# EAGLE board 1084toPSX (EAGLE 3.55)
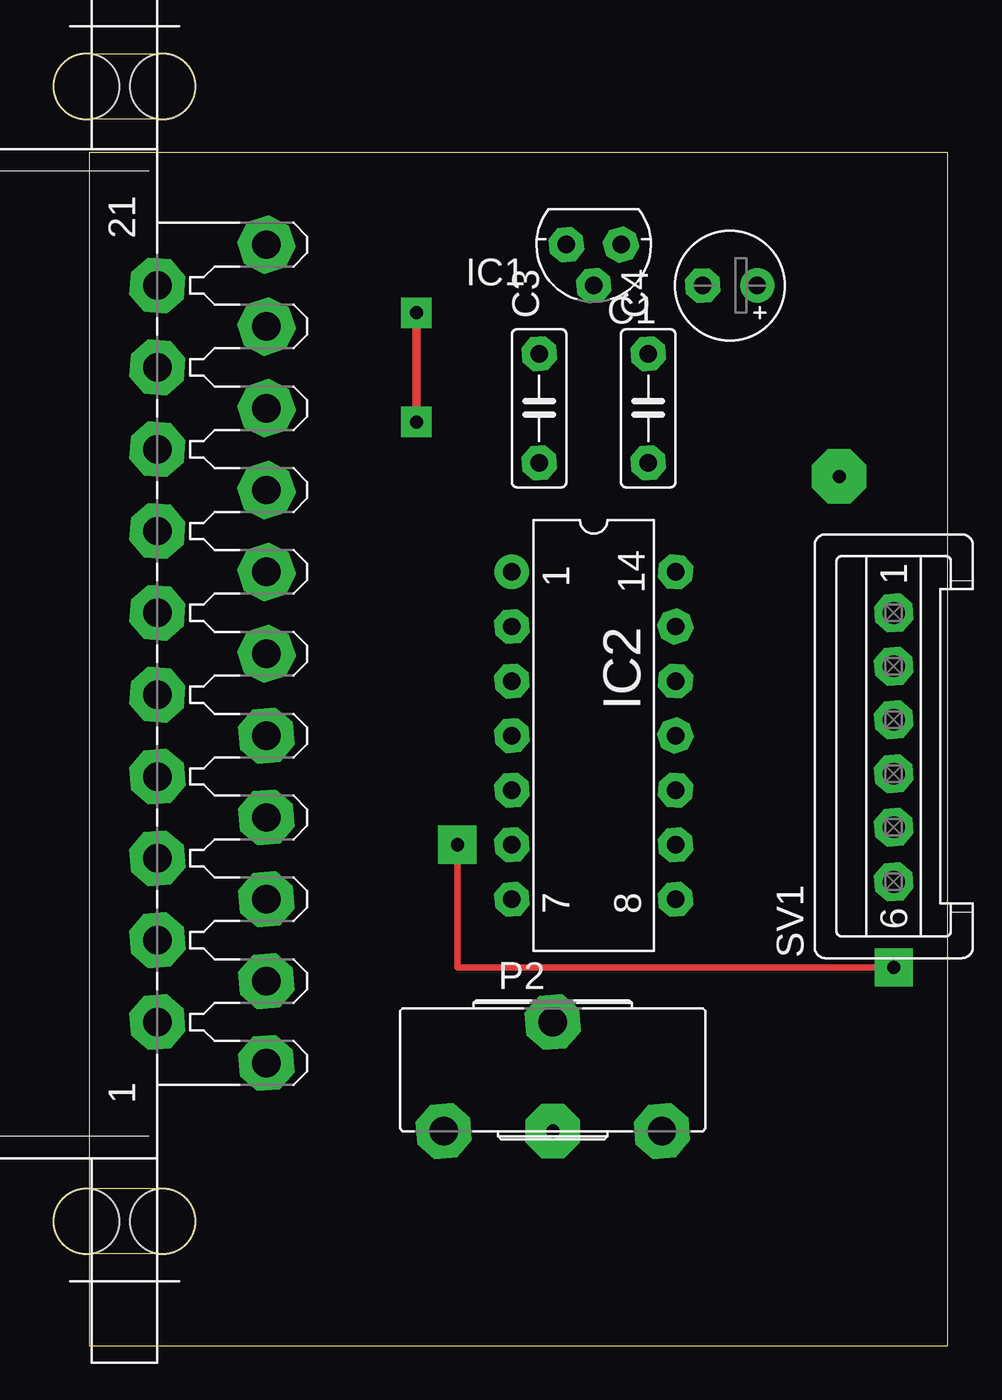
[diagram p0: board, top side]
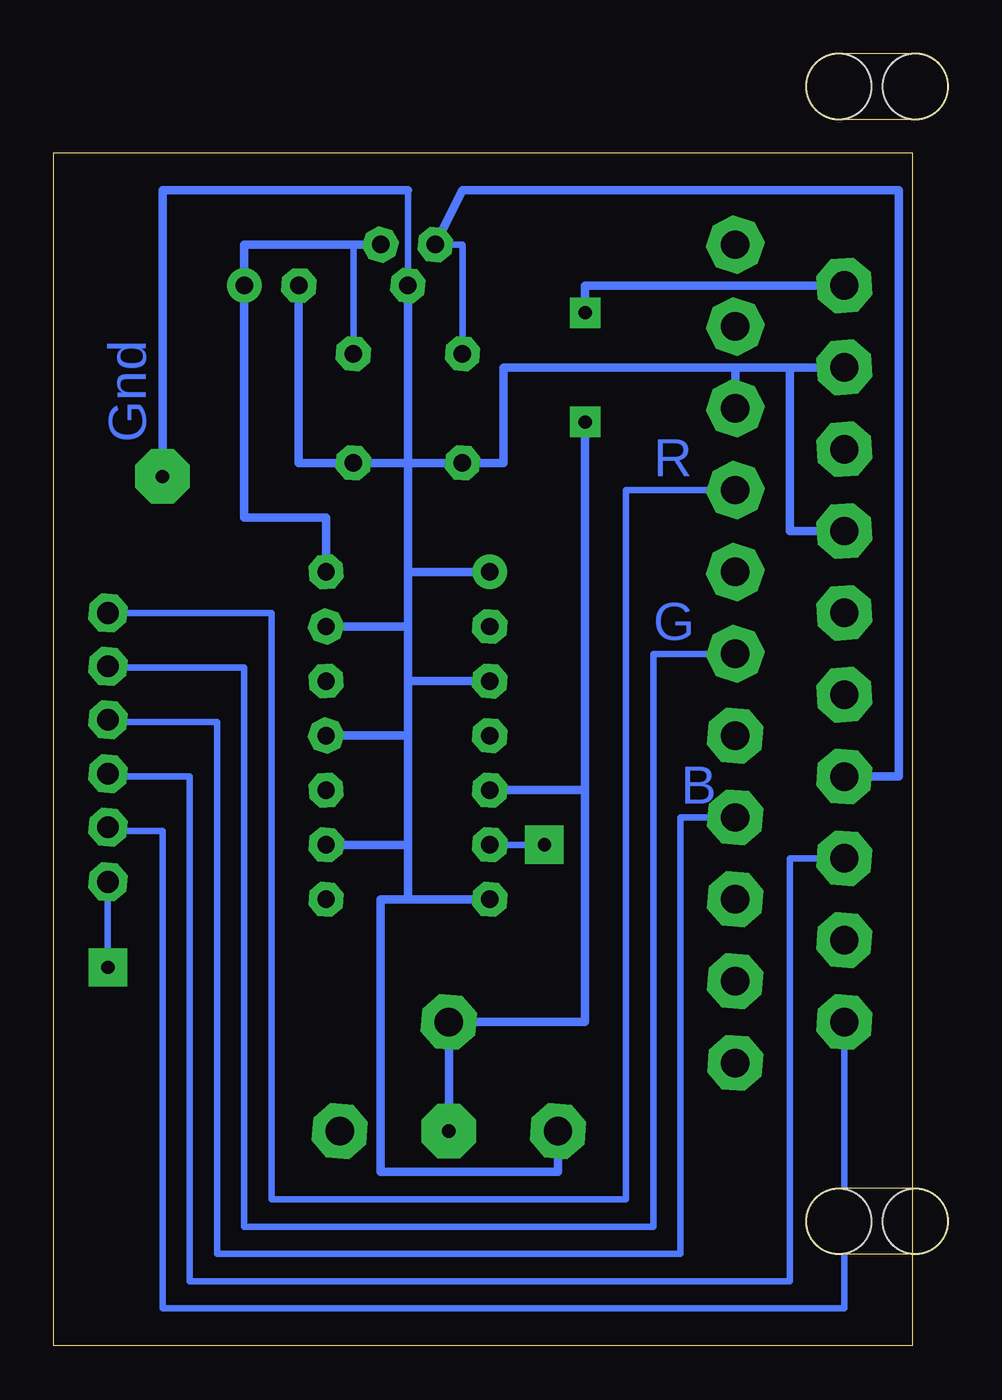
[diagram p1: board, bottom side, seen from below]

Size 41.64 x 60.16 mm. Coordinates in mm from the lower left corner, seen from the top.
Outline: 1.66,0 41.64,0 41.64,55.55 1.66,55.55 1.66,0
Copper layers used: Top, Bottom

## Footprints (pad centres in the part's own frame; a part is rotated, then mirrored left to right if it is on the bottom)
,5-5 = drill 0.813 pad 1.6 octagon:  1.27,0 | drill 0.813 pad 1.6 round:  -1.27,0
B2,5 = drill 0.813 pad 1.6 octagon:  -2.54,0;  2.54,0
LXX = drill 0.813 pad 1.6 octagon:  -1.27,0;  0,1.905;  1.27,0
L14 = drill 0.813 pad 1.6 round:  -7.62,-3.81 | drill 0.813 pad 1.6 octagon:  -5.08,-3.81;  -2.54,-3.81;  0,-3.81;  2.54,-3.81;  5.08,-3.81;  7.62,-3.81;  7.62,3.81;  5.08,3.81;  2.54,3.81;  0,3.81;  -2.54,3.81;  -5.08,3.81;  -7.62,3.81
14H = drill 1.321 pad 2.54 octagon:  -5.08,0;  0,5.08;  5.08,0
6P = drill 1.016 pad 1.778 octagon:  -4.978,0;  -12.522,0;  -9.982,0;  -7.493,0;  -2.489,0;  0,0
ART-F = drill 1.321 pad 2.54 octagon:  19.05,5.08;  17.145,0;  15.24,5.08;  13.335,0;  11.43,5.08;  9.525,0;  7.62,5.08;  5.715,0;  3.81,5.08;  1.905,0;  0,5.08;  -1.905,0;  -3.81,5.08;  -5.715,0;  -7.62,5.08;  -9.525,0;  -11.43,5.08;  -13.335,0;  -15.24,5.08;  -17.145,0;  -19.05,5.08 | hole 3.023: 26.416,0.254; 26.416,-3.302; -26.416,0.254; -26.416,-3.302

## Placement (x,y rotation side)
C1  100u  [,5-5]  31.5,49.36 180 top
C3  100n  [B2,5]  22.61,43.65 90 top
C4  100n  [B2,5]  27.69,43.65 90 top
IC1  78L05  [LXX]  25.15,51.27 180 top
IC2  7404  [L14]  25.15,28.41 270 top
P2  220 K  [14H]  23.24,10 0 top
SV1  S06P  [6P]  39.12,34.12 90 top
X1  SCART-F  [ART-F]  4.83,32.22 270 top

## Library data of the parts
C1 = polcap
C3 C4 = cap
IC1 = v-reg
IC2 = 74xx
P2 = trimpot
SV1 = con-mt
X1 = hirschm

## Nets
+5V: C1. C4. IC1. IC2.
GND: C1. C3. C4. IC1. IC2. P2. X1.
N$1: C3. IC1. X1.
N$2: SV1. X1.
N$3: IC2. SV1.
N$4: IC2. P2. X1.
N$5: SV1. X1.
N$6: SV1. X1.
N$7: SV1. X1.
N$8: SV1. X1.

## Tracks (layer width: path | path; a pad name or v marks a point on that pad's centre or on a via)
+5V
  Bottom 0.305: 26.42,51.27 27.69,51.27 C4.
  Bottom 0.406: 26.42,51.27 32.77,51.27 C1. 32.77,38.57 28.96,38.57 IC2.
GND  (via drill 0.61 pad 2.54)
  Bottom 0.305: 25.15,49.36 25.15,53.81
  Bottom 0.406: 9.91,45.55 20.7,45.55 20.7,41.11 | 9.91,45.55 9.91,43.65 | 9.91,45.55 4.83,45.55 7.37,45.55 7.37,37.93 4.83,37.93 | 20.7,41.11 22.61,41.11 25.15,41.11 | 25.15,41.11 25.15,49.36 | 25.15,41.11 27.69,41.11 30.23,41.11 30.23,49.36 | 25.15,41.11 20.7,41.11 | 25.15,36.03 25.15,41.11 | 25.15,36.03 21.34,36.03 | 25.15,33.49 28.96,33.49 | 25.15,33.49 25.15,36.03 | 25.15,30.95 21.34,30.95 | 25.15,30.95 25.15,33.49 | 25.15,20.79 25.15,23.33 | 25.15,23.33 25.15,28.41 | 25.15,28.41 25.15,30.95 | 25.15,23.33 28.96,23.33 | 25.15,28.41 28.96,28.41 | 25.15,20.79 26.42,20.79 26.42,8.09 18.16,8.09 18.16,10 | 25.15,20.79 21.34,20.79 | 25.15,53.81 36.58,53.81 v36.58,40.47
N$1
  Bottom 0.305: IC1. 22.61,51.27 C3.
  Bottom 0.406: 4.83,26.5 2.29,26.5 2.29,53.81 22.61,53.81 IC1.
N$2
  Bottom 0.305: 9.91,39.84 14.99,39.84 14.99,6.82 31.5,6.82 31.5,34.12 SV1.
N$3  (via drill 0.61 pad 1.78)
  Top 0.305: v18.8,23.33 18.8,17.61 v39.12,17.61
  Bottom 0.305: 21.34,23.33 v18.8,23.33 | 39.12,21.6 v39.12,17.61
N$4  (via drill 0.61 pad 1.42, 0.61 pad 2.54)
  Top 0.406: v16.89,43.02 v16.89,48.09
  Bottom 0.406: v23.24,10 23.24,15.07 16.89,15.07 16.89,25.87 | 16.89,25.87 21.34,25.87 | 16.89,25.87 v16.89,43.02 | v16.89,48.09 16.89,49.36 4.83,49.36
N$5
  Bottom 0.305: 9.91,32.22 13.72,32.22 13.72,5.55 32.77,5.55 32.77,31.59 39.12,31.59 39.12,31.64
N$6
  Bottom 0.305: 9.91,24.6 12.45,24.6 12.45,4.28 34.04,4.28 34.04,29.05 39.12,29.05 39.12,29.15
N$7
  Bottom 0.305: 4.83,22.7 7.37,22.7 7.37,3.01 35.31,3.01 35.31,26.5 39.12,26.5 39.12,26.63
N$8
  Bottom 0.305: 4.83,15.07 4.83,1.74 36.58,1.74 36.58,23.96 39.12,23.96 39.12,24.14
N$15  (via drill 0.61 pad 1.78)
  other vias: 18.8,23.33
N$21  (via drill 0.61 pad 1.42)
  other vias: 16.89,48.09
N$32  (via drill 0.61 pad 1.78)
  other vias: 39.12,17.61

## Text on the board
Bottom: Gnd | R | G | B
